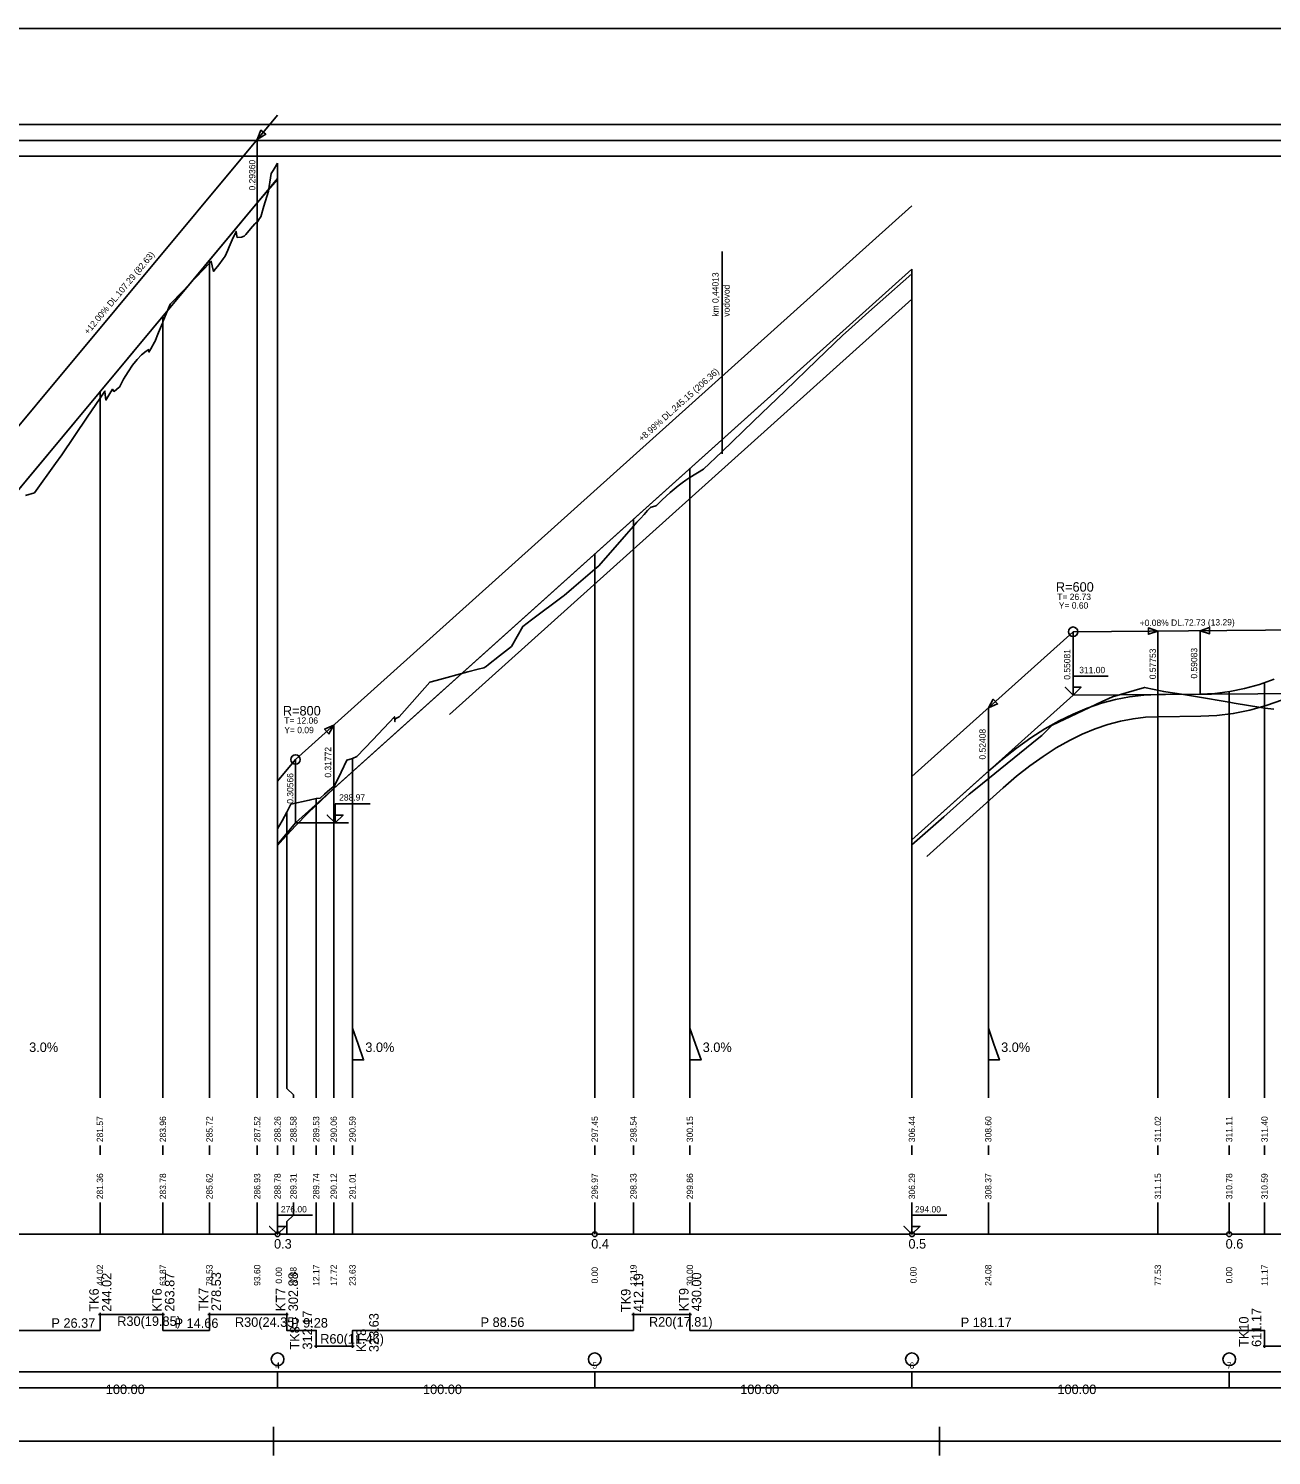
# Model space of a CAD drawing. Extents: x 1290 to 1438, y 129 to 174.
# Drawn here: x 1324.57 to 1363.75, y 128.92 to 173.92 of the extents above; entities that cross this region are included whole.
import ezdxf

# ---------------------------------------------------------------- set-up
doc = ezdxf.new("R2010")
doc.units = 0
for name, color, linetype in [('_drenaz', 7, 'Continuous'), ('KOTA', 7, 'Continuous'), ('NOVY_STAV', 7, 'Continuous'), ('NS_OBLOUK', 7, 'Continuous'), ('REZY_PO', 7, 'Continuous'), ('SESTAVY_REZU_PO', 7, 'Continuous'), ('SKLONOVE_POMERY', 7, 'Continuous'), ('SMEROVE_POMERY', 7, 'Continuous'), ('SMEROVE_POMERY_KOD', 7, 'Continuous'), ('SVK', 7, 'Continuous'), ('SVK_STAT', 7, 'Continuous'), ('TABULKY', 7, 'Continuous'), ('u_popis', 7, 'Continuous'), ('u_pricne_rezy', 7, 'Continuous'), ('x_formát_rám', 7, 'Continuous')]:
    doc.layers.add(name, color=color, linetype=linetype)

msp = doc.modelspace()

# ---------------------------------------------------------------- linework, layer by layer
at = {"layer": '_drenaz'}
for points in [[(1337.837, 152.287), (1352.417, 165.389)], [(1352.885, 147.81), (1355.287, 149.969), (1355.715, 150.338), (1356.136, 150.669), (1356.553, 150.966), (1356.967, 151.231), (1357.378, 151.463), (1357.786, 151.663), (1358.191, 151.831), (1358.592, 151.969), (1358.991, 152.075), (1359.387, 152.152), (1359.782, 152.199), (1360.188, 152.217), (1361.519, 152.228), (1362.026, 152.251), (1362.547, 152.316), (1363.065, 152.421), (1363.581, 152.566), (1364.094, 152.749)]]:
    msp.add_lwpolyline(points, dxfattribs=at)
at = {"layer": 'KOTA'}
msp.add_line((1332.983, 148.865), (1334.651, 148.865), dxfattribs=at)
for points in [[(1357.497, 152.896), (1357.247, 153.146), (1357.497, 152.896), (1357.497, 153.496), (1358.597, 153.496)], [(1357.497, 153.146), (1357.497, 152.896), (1357.747, 153.146), (1357.497, 153.146)], [(1357.497, 152.896), (1357.747, 153.146), (1357.497, 153.146)], [(1357.497, 152.896), (1357.497, 152.896)], [(1334.234, 148.865), (1333.984, 149.115), (1334.234, 148.865), (1334.234, 149.465), (1335.334, 149.465)], [(1334.234, 149.115), (1334.234, 148.865), (1334.484, 149.115), (1334.234, 149.115)], [(1334.234, 148.865), (1334.484, 149.115), (1334.234, 149.115)], [(1334.234, 148.865), (1334.234, 148.865)], [(1332.417, 135.894), (1332.167, 136.144), (1332.417, 135.894), (1332.417, 136.494), (1333.517, 136.494)], [(1352.417, 135.894), (1352.167, 136.144), (1352.417, 135.894), (1352.417, 136.494), (1353.517, 136.494)], [(1332.417, 135.894), (1332.667, 136.144), (1332.417, 136.144)], [(1352.417, 135.894), (1352.667, 136.144), (1352.417, 136.144)]]:
    msp.add_lwpolyline(points, dxfattribs=at)
at = {"layer": 'NOVY_STAV'}
for points in [[(1322.254, 158.988), (1332.417, 171.186)], [(1302.417, 147.214), (1313.777, 148.949), (1322.254, 156.988), (1332.417, 169.186)], [(1302.417, 147.214), (1311.39, 148.584), (1311.824, 148.666), (1312.258, 148.78), (1312.692, 148.924), (1313.126, 149.101), (1313.56, 149.308), (1313.994, 149.547), (1314.428, 149.817), (1314.862, 150.119), (1315.296, 150.452), (1315.73, 150.816), (1316.164, 151.212), (1320.994, 155.793), (1321.414, 156.2), (1321.834, 156.625), (1322.254, 157.067), (1322.674, 157.527), (1323.094, 158.004), (1323.514, 158.5), (1331.777, 168.418), (1332.179, 168.89), (1332.417, 169.158)], [(1332.983, 150.865), (1352.417, 168.331)], [(1332.417, 148.186), (1332.983, 148.865), (1352.417, 166.331)], [(1332.417, 148.158), (1332.581, 148.342), (1332.983, 148.774), (1333.385, 149.186), (1333.787, 149.578), (1334.189, 149.95), (1352.417, 166.331)], [(1352.417, 148.331), (1357.497, 152.896), (1364.77, 152.953), (1371.787, 160.658), (1380.986, 165.882), (1389.751, 163.594), (1398.36, 163.097), (1406.284, 157.825), (1410.009, 157.782)], [(1352.417, 150.331), (1357.497, 154.896)], [(1357.497, 154.896), (1364.77, 154.953)], [(1357.497, 152.896), (1357.497, 154.896)], [(1352.417, 148.331), (1354.825, 150.494), (1355.27, 150.878), (1355.716, 151.229), (1356.161, 151.547), (1356.606, 151.831), (1357.052, 152.083), (1357.497, 152.301), (1357.943, 152.486), (1358.388, 152.639), (1358.834, 152.758), (1359.279, 152.844), (1359.725, 152.897), (1360.17, 152.917), (1361.5, 152.928), (1361.967, 152.949), (1362.434, 153.008), (1362.901, 153.102), (1363.368, 153.233), (1363.836, 153.4)], [(1332.417, 150.186), (1332.983, 150.865)], [(1332.983, 148.865), (1332.983, 150.865)]]:
    msp.add_lwpolyline(points, dxfattribs=at)
for centre in [(1357.497, 154.896), (1332.983, 150.865)]:
    msp.add_circle(centre, 0.15, dxfattribs=at)
at = {"layer": 'NS_OBLOUK'}
for points in [[(1331.777, 170.418), (1332.045, 170.584), (1331.892, 170.712), (1331.777, 170.418)], [(1331.777, 168.418), (1331.777, 170.418)], [(1359.871, 154.815), (1360.17, 154.917), (1359.869, 155.015), (1359.871, 154.815)], [(1360.17, 152.917), (1360.17, 154.917)], [(1361.5, 154.928), (1361.8, 154.83), (1361.799, 155.03), (1361.5, 154.928)], [(1361.5, 152.928), (1361.5, 154.928)], [(1354.825, 152.494), (1355.115, 152.621), (1354.981, 152.769), (1354.825, 152.494)], [(1354.825, 150.494), (1354.825, 152.494)], [(1334.033, 151.675), (1334.189, 151.95), (1333.899, 151.823), (1334.033, 151.675)], [(1334.189, 149.95), (1334.189, 151.95)]]:
    msp.add_lwpolyline(points, dxfattribs=at)
for points in [[(1331.777, 170.418), (1331.892, 170.712), (1332.045, 170.584)], [(1360.17, 154.917), (1359.869, 155.015), (1359.871, 154.815)], [(1361.5, 154.928), (1361.799, 155.03), (1361.8, 154.83)], [(1354.825, 152.494), (1354.981, 152.769), (1355.115, 152.621)], [(1334.189, 151.95), (1333.899, 151.823), (1334.033, 151.675)]]:
    msp.add_lwpolyline(points, close=True, dxfattribs=at)
at = {"layer": 'REZY_PO'}
for points in [[(1324.467, 159.188), (1324.75, 159.278), (1325.417, 160.198), (1325.618, 160.475), (1326.417, 161.661), (1326.819, 162.257), (1326.83, 162.274), (1326.842, 162.291), (1326.972, 162.483), (1326.986, 162.375), (1327.007, 162.203), (1327.129, 162.406), (1327.211, 162.545), (1327.255, 162.474), (1327.273, 162.487), (1327.417, 162.599), (1327.428, 162.609), (1327.56, 162.856), (1327.703, 163.094), (1327.845, 163.302), (1327.988, 163.481), (1328.131, 163.629), (1328.274, 163.747), (1328.353, 163.794), (1328.358, 163.715), (1328.417, 163.821), (1328.54, 164.033), (1328.542, 164.035), (1328.664, 164.328), (1328.788, 164.629), (1328.796, 164.649), (1328.804, 164.669), (1329.028, 165.222), (1329.417, 165.627), (1330.27, 166.518), (1330.283, 166.532), (1330.296, 166.545), (1330.325, 166.574), (1330.357, 166.434), (1330.396, 166.257), (1330.417, 166.284), (1330.56, 166.467), (1330.703, 166.658), (1330.76, 166.737), (1330.845, 166.934), (1330.885, 167.033), (1330.988, 167.254), (1331.106, 167.521), (1331.131, 167.375), (1331.14, 167.332), (1331.274, 167.344), (1331.368, 167.367), (1331.417, 167.428), (1331.56, 167.601), (1331.703, 167.764), (1331.717, 167.78), (1331.779, 167.827), (1331.845, 167.923), (1331.884, 167.977), (1331.988, 168.314), (1332.129, 168.785), (1332.131, 168.802), (1332.214, 169.352), (1332.274, 169.443), (1332.417, 169.678)], [(1332.417, 148.678), (1332.417, 148.678), (1332.417, 148.678), (1332.561, 148.931), (1332.705, 149.203), (1332.836, 149.456), (1333.417, 149.584), (1333.634, 149.632), (1333.764, 149.652), (1333.764, 149.652), (1333.894, 149.769), (1334.068, 149.918), (1334.215, 150.036), (1334.243, 150.097), (1334.417, 150.469), (1334.595, 150.841), (1334.599, 150.842), (1334.78, 150.901), (1334.919, 150.958), (1335.417, 151.487), (1336.1, 152.213), (1336.115, 152.064), (1336.119, 152.149), (1336.252, 152.215), (1336.417, 152.4), (1337.22, 153.304), (1337.417, 153.357), (1338.417, 153.629), (1338.736, 153.716), (1338.919, 153.758), (1338.923, 153.76), (1338.993, 153.804), (1339.07, 153.858), (1339.417, 154.137), (1339.693, 154.359), (1339.786, 154.431), (1340.144, 155.058), (1340.146, 155.061), (1340.149, 155.065), (1340.417, 155.267), (1341.417, 156.02), (1341.447, 156.042), (1341.756, 156.306), (1342.417, 156.868), (1342.546, 156.977), (1343.417, 157.971), (1343.636, 158.221), (1343.636, 158.221), (1343.636, 158.221), (1343.747, 158.348), (1343.859, 158.472), (1343.97, 158.595), (1344.082, 158.715), (1344.177, 158.814), (1344.194, 158.82), (1344.305, 158.857), (1344.358, 158.872), (1344.417, 158.932), (1344.542, 159.054), (1344.667, 159.172), (1344.792, 159.285), (1344.917, 159.392), (1345.042, 159.494), (1345.167, 159.588), (1345.292, 159.677), (1345.417, 159.757), (1345.417, 159.758), (1345.849, 160.026), (1346.417, 160.572), (1347.417, 161.535), (1348.417, 162.498), (1349.417, 163.461), (1350.239, 164.253), (1350.417, 164.411), (1351.06, 164.981), (1351.417, 165.296), (1352.417, 166.179), (1352.417, 166.179)], [(1352.417, 148.179), (1352.417, 148.179), (1353.417, 149.062), (1354.221, 149.772), (1354.417, 149.931), (1355.417, 150.741), (1356.417, 151.551), (1356.51, 151.626), (1356.836, 151.946), (1357.417, 152.22), (1358.417, 152.691), (1358.743, 152.845), (1359.417, 153.041), (1359.749, 153.138), (1360.352, 153.007), (1360.417, 152.997), (1360.917, 152.922), (1361.417, 152.839), (1362.417, 152.672), (1362.577, 152.646), (1363.417, 152.506), (1363.534, 152.487), (1363.534, 152.487), (1363.534, 152.487), (1363.632, 152.472), (1363.73, 152.463), (1363.828, 152.459)]]:
    msp.add_lwpolyline(points, dxfattribs=at)
at = {"layer": 'SESTAVY_REZU_PO'}
for points in [[(1322.492, 135.894), (1332.342, 135.894)], [(1332.492, 135.894), (1342.342, 135.894)], [(1342.492, 135.894), (1352.342, 135.894)], [(1352.492, 135.894), (1362.342, 135.894)], [(1362.492, 135.894), (1372.342, 135.894)]]:
    msp.add_lwpolyline(points, dxfattribs=at)
for centre in [(1332.417, 135.894), (1342.417, 135.894), (1352.417, 135.894), (1362.417, 135.894)]:
    msp.add_circle(centre, 0.075, dxfattribs=at)
at = {"layer": 'SKLONOVE_POMERY'}
for points in [[(1334.78, 141.394), (1334.78, 142.394), (1334.78, 142.394), (1334.955, 141.894), (1335.13, 141.394), (1334.78, 141.394)], [(1345.417, 141.394), (1345.417, 142.394), (1345.417, 142.394), (1345.592, 141.894), (1345.767, 141.394), (1345.417, 141.394)], [(1354.825, 141.394), (1354.825, 142.394), (1354.825, 142.394), (1355, 141.894), (1355.175, 141.394), (1354.825, 141.394)]]:
    msp.add_lwpolyline(points, dxfattribs=at)
at = {"layer": 'SMEROVE_POMERY'}
msp.add_lwpolyline([(1324.182, 132.862), (1326.819, 132.862), (1326.819, 133.362), (1328.804, 133.362), (1328.804, 132.862), (1330.27, 132.862), (1330.27, 133.362), (1332.705, 133.362), (1332.705, 132.862), (1333.634, 132.862), (1333.634, 132.362), (1334.78, 132.362), (1334.78, 132.862), (1343.636, 132.862), (1343.636, 133.362), (1345.417, 133.362), (1345.417, 132.862), (1363.534, 132.862), (1363.534, 132.362), (1365.494, 132.362)], dxfattribs=at)
at = {"layer": 'SMEROVE_POMERY_KOD'}
for points in [[(1326.769, 133.362), (1326.869, 133.362)], [(1326.819, 133.312), (1326.819, 133.412)], [(1328.754, 133.362), (1328.854, 133.362)], [(1328.804, 133.312), (1328.804, 133.412)], [(1330.22, 133.362), (1330.32, 133.362)], [(1330.27, 133.312), (1330.27, 133.412)], [(1332.655, 133.362), (1332.755, 133.362)], [(1332.705, 133.312), (1332.705, 133.412)], [(1343.586, 133.362), (1343.686, 133.362)], [(1343.636, 133.312), (1343.636, 133.412)], [(1345.367, 133.362), (1345.467, 133.362)], [(1345.417, 133.312), (1345.417, 133.412)], [(1333.584, 132.362), (1333.684, 132.362)], [(1333.634, 132.312), (1333.634, 132.412)], [(1334.73, 132.362), (1334.83, 132.362)], [(1334.78, 132.312), (1334.78, 132.412)], [(1363.484, 132.362), (1363.584, 132.362)], [(1363.534, 132.312), (1363.534, 132.412)]]:
    msp.add_lwpolyline(points, dxfattribs=at)
at = {"layer": 'SVK'}
for points in [[(1332.417, 140.194), (1332.417, 169.678)], [(1352.417, 140.194), (1352.417, 166.331)], [(1332.417, 138.394), (1332.417, 138.694)], [(1352.417, 138.394), (1352.417, 138.694)], [(1332.417, 135.894), (1332.417, 136.894)], [(1352.417, 135.894), (1352.417, 136.894)]]:
    msp.add_lwpolyline(points, dxfattribs=at)
at = {"layer": 'SVK_STAT'}
for points in [[(1331.777, 140.194), (1331.777, 168.418)], [(1330.27, 140.194), (1330.27, 166.61)], [(1328.804, 140.194), (1328.804, 164.85)], [(1326.819, 140.194), (1326.819, 162.467)], [(1345.417, 140.194), (1345.417, 160.039)], [(1343.636, 140.194), (1343.636, 158.439)], [(1342.417, 140.194), (1342.417, 157.344)], [(1360.17, 140.194), (1360.17, 153.046)], [(1362.417, 140.194), (1362.417, 153.005)], [(1363.534, 140.194), (1363.534, 153.292)], [(1334.78, 140.194), (1334.78, 150.901)], [(1354.825, 140.194), (1354.825, 150.494)], [(1334.189, 140.194), (1334.189, 150.015)], [(1333.634, 140.194), (1333.634, 149.632)], [(1332.917, 140.194), (1332.917, 140.294), (1332.705, 140.494), (1332.705, 149.203)], [(1326.819, 138.394), (1326.819, 138.694)], [(1328.804, 138.394), (1328.804, 138.694)], [(1330.27, 138.394), (1330.27, 138.694)], [(1331.777, 138.394), (1331.777, 138.694)], [(1332.917, 138.394), (1332.917, 138.694)], [(1333.634, 138.394), (1333.634, 138.694)], [(1334.189, 138.394), (1334.189, 138.694)], [(1334.78, 138.394), (1334.78, 138.694)], [(1342.417, 138.394), (1342.417, 138.694)], [(1343.636, 138.394), (1343.636, 138.694)], [(1345.417, 138.394), (1345.417, 138.694)], [(1354.825, 138.394), (1354.825, 138.694)], [(1360.17, 138.394), (1360.17, 138.694)], [(1362.417, 138.394), (1362.417, 138.694)], [(1363.534, 138.394), (1363.534, 138.694)], [(1326.819, 135.894), (1326.819, 136.894)], [(1328.804, 135.894), (1328.804, 136.894)], [(1330.27, 135.894), (1330.27, 136.894)], [(1331.777, 135.894), (1331.777, 136.894)], [(1332.705, 135.894), (1332.705, 136.294), (1332.917, 136.494), (1332.917, 136.894)], [(1333.634, 135.894), (1333.634, 136.894)], [(1334.189, 135.894), (1334.189, 136.894)], [(1334.78, 135.894), (1334.78, 136.894)], [(1342.417, 135.894), (1342.417, 136.894)], [(1343.636, 135.894), (1343.636, 136.894)], [(1345.417, 135.894), (1345.417, 136.894)], [(1354.825, 135.894), (1354.825, 136.894)], [(1360.17, 135.894), (1360.17, 136.894)], [(1362.417, 135.894), (1362.417, 136.894)], [(1363.534, 135.894), (1363.534, 136.894)]]:
    msp.add_lwpolyline(points, dxfattribs=at)
at = {"layer": 'TABULKY'}
for points in [[(1302.417, 169.89), (1410.009, 169.89), (1410.009, 170.89), (1302.417, 170.89), (1302.417, 169.89)], [(1302.417, 170.39), (1410.009, 170.39)]]:
    msp.add_lwpolyline(points, dxfattribs=at)
at = {"layer": 'u_popis'}
msp.add_lwpolyline([(1346.43, 160.511), (1346.43, 166.882)], dxfattribs=at)
at = {"layer": 'u_pricne_rezy'}
for points in [[(1302.417, 131.054), (1410.009, 131.054), (1410.009, 131.554), (1302.417, 131.554), (1302.417, 131.054)], [(1332.417, 131.054), (1332.417, 131.554)], [(1342.417, 131.054), (1342.417, 131.554)], [(1352.417, 131.054), (1352.417, 131.554)], [(1362.417, 131.054), (1362.417, 131.554)]]:
    msp.add_lwpolyline(points, dxfattribs=at)
for centre in [(1332.417, 131.954), (1342.417, 131.954), (1352.417, 131.954), (1362.417, 131.954)]:
    msp.add_circle(centre, 0.2, dxfattribs=at)
at = {"layer": 'x_formát_rám'}
for p, q in [((1332.283, 128.918), (1332.283, 129.818)), ((1353.283, 128.918), (1353.283, 129.818))]:
    msp.add_line(p, q, dxfattribs=at)
msp.add_lwpolyline([(1290.283, 129.368), (1437.283, 129.368), (1437.283, 173.918), (1290.283, 173.918)], close=True, dxfattribs=at)

# ---------------------------------------------------------------- texts
at = {"layer": 'KOTA'}
for s, p in [('311.00', (1357.689, 153.588)), ('288.97', (1334.358, 149.572)), ('276.00', (1332.521, 136.583)), ('294.00', (1352.512, 136.581))]:
    msp.add_text(s, height=0.2, dxfattribs=at).set_placement(p)
at = {"layer": 'NOVY_STAV'}
for s, rotation, p in [('+12.00% DL.107.29 (82.63)', 50.2008, (1326.447, 164.252)), ('+8.99% DL.245.15 (206.36)', 41.9456, (1343.904, 160.878)), ('+0.08% DL.72.73 (13.29)', 0.4465, (1359.597, 155.074)), (' 0.55081', 90, (1357.409, 153.307)), (' 0.30566', 90, (1332.914, 149.397))]:
    msp.add_text(s, height=0.2, rotation=rotation, dxfattribs=at).set_placement(p)
at = {"layer": 'NS_OBLOUK'}
for s, p in [(' 0.29360', (1331.716, 168.737)), (' 0.57753', (1360.106, 153.323)), (' 0.59083', (1361.41, 153.344)), (' 0.52408', (1354.74, 150.79)), (' 0.31772', (1334.106, 150.221))]:
    msp.add_text(s, height=0.2, rotation=90, dxfattribs=at).set_placement(p)
for s, height, p in [('R=600', 0.3, (1356.954, 156.159)), ('T= 26.73', 0.2, (1356.997, 155.896)), ('Y= 0.60', 0.2, (1357.046, 155.625)), ('R=800', 0.3, (1332.584, 152.254)), ('T= 12.06', 0.2, (1332.628, 151.996)), ('Y= 0.09', 0.2, (1332.628, 151.696))]:
    msp.add_text(s, height=height, dxfattribs=at).set_placement(p)
at = {"layer": 'SESTAVY_REZU_PO'}
for s, p in [('0.3', (1332.305, 135.442)), ('0.4', (1342.305, 135.442)), ('0.5', (1352.305, 135.442)), ('0.6', (1362.305, 135.442))]:
    msp.add_text(s, height=0.3, dxfattribs=at).set_placement(p)
at = {"layer": 'SKLONOVE_POMERY'}
for p in [(1324.584, 141.642), (1335.183, 141.642), (1345.819, 141.642), (1355.227, 141.642)]:
    msp.add_text('3.0%', height=0.3, dxfattribs=at).set_placement(p)
at = {"layer": 'SMEROVE_POMERY'}
for s, p in [('P 26.37', (1325.287, 132.945)), ('R30(19.85)', (1327.362, 133.003)), ('P 14.66', (1329.169, 132.942)), ('R30(24.35)', (1331.072, 132.974)), ('P 9.28', (1332.843, 132.952)), ('P 88.56', (1338.816, 132.971)), ('R20(17.81)', (1344.125, 132.983)), ('P 181.17', (1353.955, 132.967)), ('R60(11.46)', (1333.762, 132.447))]:
    msp.add_text(s, height=0.3, dxfattribs=at).set_placement(p)
at = {"layer": 'SMEROVE_POMERY_KOD'}
for s, p in [('244.02', (1327.179, 133.452)), ('263.87', (1329.164, 133.455)), ('278.53', (1330.63, 133.472)), ('302.88', (1333.06, 133.467)), ('412.19', (1343.943, 133.438)), ('430.00', (1345.774, 133.464)), ('TK6', (1326.779, 133.452)), ('KT6', (1328.764, 133.455)), ('TK7', (1330.23, 133.472)), ('KT7', (1332.66, 133.467)), ('TK9', (1343.543, 133.438)), ('KT9', (1345.374, 133.464)), ('312.17', (1333.505, 132.259)), ('323.63', (1335.604, 132.179)), ('TK10', (1363.027, 132.342)), ('611.17', (1363.427, 132.342)), ('TK8', (1333.105, 132.259)), ('KT8', (1335.204, 132.179))]:
    msp.add_text(s, height=0.3, rotation=90, dxfattribs=at).set_placement(p)
at = {"layer": 'SVK'}
for s, p in [(' 288.26', (1332.514, 138.724)), (' 306.44', (1352.514, 138.724)), (' 288.78', (1332.514, 136.924)), (' 306.29', (1352.514, 136.924))]:
    msp.add_text(s, height=0.2, rotation=90, dxfattribs=at).set_placement(p)
at = {"layer": 'SVK_STAT'}
for s, p in [(' 281.57', (1326.916, 138.724)), (' 283.96', (1328.901, 138.724)), (' 285.72', (1330.367, 138.724)), (' 287.52', (1331.874, 138.724)), (' 288.58', (1333.014, 138.724)), (' 289.53', (1333.731, 138.724)), (' 290.06', (1334.286, 138.724)), (' 290.59', (1334.877, 138.724)), (' 297.45', (1342.514, 138.724)), (' 298.54', (1343.733, 138.724)), (' 300.15', (1345.514, 138.724)), (' 308.60', (1354.922, 138.724)), (' 311.02', (1360.267, 138.724)), (' 311.11', (1362.514, 138.724)), (' 311.40', (1363.631, 138.724)), (' 281.36', (1326.916, 136.924)), (' 283.78', (1328.901, 136.924)), (' 285.62', (1330.367, 136.924)), (' 286.93', (1331.874, 136.924)), (' 289.31', (1333.014, 136.924)), (' 289.74', (1333.731, 136.924)), (' 290.12', (1334.286, 136.924)), (' 291.01', (1334.877, 136.924)), (' 296.97', (1342.514, 136.924)), (' 298.33', (1343.733, 136.924)), (' 299.86', (1345.514, 136.924)), (' 308.37', (1354.922, 136.924)), (' 311.15', (1360.267, 136.924)), (' 310.78', (1362.514, 136.924)), (' 310.59', (1363.631, 136.924)), (' 44.02', (1326.916, 134.194)), (' 63.87', (1328.901, 134.194)), (' 78.53', (1330.367, 134.194)), (' 93.60', (1331.874, 134.194)), ('  0.00', (1332.556, 134.189)), ('  2.88', (1333.014, 134.194)), (' 12.17', (1333.731, 134.194)), (' 17.72', (1334.286, 134.194)), (' 23.63', (1334.877, 134.194)), ('  0.00', (1342.514, 134.194)), (' 12.19', (1343.733, 134.194)), (' 30.00', (1345.514, 134.194)), ('  0.00', (1352.561, 134.199)), (' 24.08', (1354.922, 134.194)), (' 77.53', (1360.267, 134.194)), ('  0.00', (1362.514, 134.194)), (' 11.17', (1363.631, 134.194))]:
    msp.add_text(s, height=0.2, rotation=90, dxfattribs=at).set_placement(p)
at = {"layer": 'u_popis'}
for s, p in [('km 0,44013', (1346.319, 164.831)), ('vodovod', (1346.669, 164.831))]:
    msp.add_text(s, height=0.2, rotation=90, dxfattribs=at).set_placement(p)
at = {"layer": 'u_pricne_rezy'}
for s, height, p in [('4', 0.2, (1332.342, 131.654)), ('5', 0.2, (1342.342, 131.654)), ('6', 0.2, (1352.342, 131.654)), ('7', 0.2, (1362.342, 131.654)), ('100.00', 0.3, (1327.002, 130.854)), ('100.00', 0.3, (1337.002, 130.854)), ('100.00', 0.3, (1347.002, 130.854)), ('100.00', 0.3, (1357.002, 130.854))]:
    msp.add_text(s, height=height, dxfattribs=at).set_placement(p)

doc.saveas('drawing.dxf')
